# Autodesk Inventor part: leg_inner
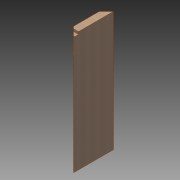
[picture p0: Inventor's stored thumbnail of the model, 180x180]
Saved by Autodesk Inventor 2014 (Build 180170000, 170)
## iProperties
Created: 2014-05
Part Number: leg_inner
Material: Maple
Document SubType Name: Modeling
Designer: t_emanb
Density: 1 g/cm^3
Appearance: Maple - Solid Natural Medium Gloss
Author: t_emanb
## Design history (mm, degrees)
sketch "Sketch1"
  geometry: L1 (0, 0)-(-18.034, 0); L2 (-18.034, 0)-(-18.034, -101.6); L3 (-18.034, -101.6)-(0, -101.6); L4 (0, -101.6)-(0, 0)
  constraints: 8 end point, 2 parallel, 1 horizontal, 1 perpendicular
  dimensions: "d0" = 101.6 distance of L3.end L1.start; "d1" = 18.034 distance of L1.start L1.end
extrude "Extrusion1" new body sketch "Sketch1" distance "d2" = 304.8; taper "d3" = 0 deg
sketch "Sketch2"
  geometry: L1 (0, 0)-(18.034, 0) reference; L2 (18.034, 101.6)-(0, 101.6) reference; L3 (0, 101.6)-(0, 0) reference; L4 (18.034, 101.6)-(0, 83.566); L5 (18.034, 0)-(0, 18.034)
  constraints: 4 end point, 2 point on line
  dimensions: "d4" = 45 deg angle of L1 L5; "d5" = 45 deg angle of L2 L4
extrude "Extrusion2" cut sketch "Sketch2" stored distance "d6" = 304.8; taper "d7" = 0 deg
sketch "Sketch5"
  geometry: L1 (0, 18.034)-(18.034, 0) reference; L2 (18.034, 0)-(18.034, 101.6) reference; L3 (0, 83.566)-(0, 18.034) reference; L4 (18.034, 12.7)-(5.334, 12.7); 1 further point
  constraints: 2 end point, 2 point on line, 1 perpendicular
  dimensions: "d14" = 12.7 distance from line of point (0, 0) L4
extrude "Extrusion5" cut sketch "Sketch5" distance "d15" = 6.35; taper "d16" = 0 deg
sketch "Sketch4"
  geometry: L1 (0, 18.034)-(18.034, 0) reference; L2 (18.034, 0)-(18.034, 101.6) reference; L3 (0, 83.566)-(0, 18.034) reference; L4 (18.034, 3.099)-(14.935, 3.099); 1 further point
  constraints: 2 end point, 2 point on line, 1 perpendicular
  dimensions: "d11" = 3.0988 distance from line of point (0, 0) L4
extrude "Extrusion4" cut sketch "Sketch4" distance "d12" = 44.45; taper "d13" = 0 deg
body "Solid1"
